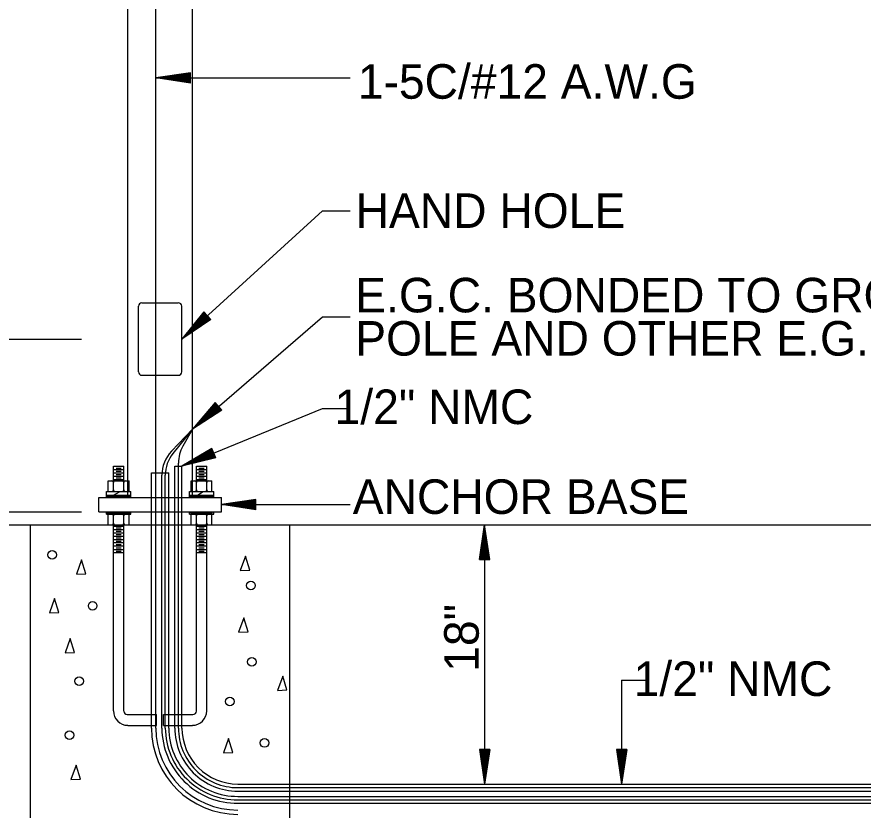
# Model space of a CAD drawing. Extents: x 1695551 to 1695718, y 544410 to 544516.
# Drawn here: x 1695569.58 to 1695587.94, y 544481.31 to 544498.53 of the extents above; entities that cross this region are included whole.
import ezdxf

# ---------------------------------------------------------------- set-up
doc = ezdxf.new("R2010")
doc.units = 0
doc.layers.add('R_Draft', color=7, linetype='Continuous')

msp = doc.modelspace()

# ---------------------------------------------------------------- linework, layer by layer
at = {"layer": 'R_Draft'}
for p, q in [((1695571.983, 544488.101), (1695571.983, 544503.214)), ((1695573.389, 544488.101), (1695573.389, 544503.214)), ((1695572.592, 544483.092), (1695572.592, 544499.584)), ((1695573.343, 544497.321), (1695572.593, 544497.209)), ((1695572.593, 544497.209), (1695576.808, 544497.209)), ((1695573.343, 544497.096), (1695572.593, 544497.209)), ((1695573.343, 544497.302), (1695572.719, 544497.209)), ((1695573.343, 544497.115), (1695572.719, 544497.209)), ((1695573.343, 544497.283), (1695572.848, 544497.209)), ((1695573.343, 544497.134), (1695572.848, 544497.209)), ((1695573.343, 544497.265), (1695572.972, 544497.209)), ((1695573.343, 544497.153), (1695572.972, 544497.209)), ((1695573.343, 544497.245), (1695573.1, 544497.209)), ((1695573.343, 544497.172), (1695573.1, 544497.209)), ((1695573.343, 544497.226), (1695573.225, 544497.209)), ((1695573.343, 544497.191), (1695573.225, 544497.209)), ((1695573.343, 544497.096), (1695573.343, 544497.321)), ((1695573.155, 544491.538), (1695576.207, 544494.32)), ((1695576.207, 544494.32), (1695576.808, 544494.32)), ((1695572.217, 544490.826), (1695572.217, 544492.251)), ((1695572.292, 544492.326), (1695573.08, 544492.326)), ((1695573.155, 544490.826), (1695573.155, 544492.251)), ((1695573.633, 544492.127), (1695573.155, 544491.538)), ((1695573.646, 544492.113), (1695573.247, 544491.623)), ((1695573.658, 544492.099), (1695573.343, 544491.71)), ((1695573.389, 544489.581), (1695576.207, 544492.019)), ((1695573.671, 544492.085), (1695573.435, 544491.794)), ((1695573.684, 544492.071), (1695573.529, 544491.88)), ((1695573.733, 544492.017), (1695573.529, 544491.88)), ((1695573.697, 544492.057), (1695573.621, 544491.964)), ((1695573.721, 544492.031), (1695573.621, 544491.964)), ((1695573.785, 544491.961), (1695573.633, 544492.127)), ((1695576.207, 544492.019), (1695576.808, 544492.019)), ((1695573.785, 544491.961), (1695573.155, 544491.538)), ((1695573.772, 544491.975), (1695573.247, 544491.623)), ((1695573.759, 544491.989), (1695573.343, 544491.71)), ((1695573.746, 544492.003), (1695573.435, 544491.794)), ((1695568.796, 544491.538), (1695570.98, 544491.538)), ((1695572.292, 544490.751), (1695573.08, 544490.751)), ((1695573.161, 544488.775), (1695576.207, 544490.032)), ((1695573.879, 544490.16), (1695573.389, 544489.581)), ((1695574.028, 544489.991), (1695573.389, 544489.581)), ((1695573.892, 544490.146), (1695573.484, 544489.664)), ((1695574.015, 544490.005), (1695573.484, 544489.664)), ((1695573.904, 544490.132), (1695573.581, 544489.749)), ((1695574.003, 544490.019), (1695573.581, 544489.749)), ((1695573.917, 544490.118), (1695573.675, 544489.831)), ((1695573.99, 544490.034), (1695573.675, 544489.831)), ((1695573.929, 544490.103), (1695573.77, 544489.915)), ((1695573.978, 544490.048), (1695573.77, 544489.915)), ((1695573.942, 544490.089), (1695573.864, 544489.998)), ((1695573.965, 544490.062), (1695573.864, 544489.998)), ((1695574.028, 544489.991), (1695573.879, 544490.16)), ((1695576.207, 544490.032), (1695576.808, 544490.032)), ((1695573.389, 544489.581), (1695572.931, 544489.102)), ((1695573.389, 544489.581), (1695572.965, 544489.055)), ((1695573.389, 544489.581), (1695573.181, 544489.214)), ((1695573.812, 544489.165), (1695573.161, 544488.775)), ((1695573.819, 544489.148), (1695573.277, 544488.823)), ((1695573.826, 544489.13), (1695573.396, 544488.872)), ((1695573.833, 544489.113), (1695573.512, 544488.92)), ((1695573.841, 544489.095), (1695573.629, 544488.968)), ((1695573.848, 544489.078), (1695573.745, 544489.016)), ((1695573.897, 544488.957), (1695573.812, 544489.165)), ((1695573.897, 544488.957), (1695573.161, 544488.775)), ((1695573.89, 544488.975), (1695573.277, 544488.823)), ((1695573.883, 544488.992), (1695573.396, 544488.872)), ((1695573.876, 544489.01), (1695573.512, 544488.92)), ((1695573.868, 544489.028), (1695573.629, 544488.968)), ((1695573.861, 544489.045), (1695573.745, 544489.016)), ((1695571.674, 544488.775), (1695571.899, 544488.775)), ((1695571.674, 544488.463), (1695571.674, 544488.775)), ((1695571.674, 544488.703), (1695571.899, 544488.703)), ((1695571.73, 544488.738), (1695571.842, 544488.738)), ((1695571.899, 544488.463), (1695571.899, 544488.775)), ((1695573.005, 544483.092), (1695573.005, 544488.775)), ((1695573.005, 544488.775), (1695573.161, 544488.775)), ((1695573.083, 544483.092), (1695573.083, 544488.844)), ((1695573.161, 544483.092), (1695573.161, 544488.775)), ((1695573.474, 544488.775), (1695573.699, 544488.775)), ((1695573.474, 544488.463), (1695573.474, 544488.775)), ((1695573.474, 544488.703), (1695573.699, 544488.703)), ((1695573.53, 544488.738), (1695573.642, 544488.738)), ((1695573.699, 544488.463), (1695573.699, 544488.775)), ((1695571.674, 544488.631), (1695571.899, 544488.631)), ((1695571.674, 544488.559), (1695571.899, 544488.559)), ((1695571.73, 544488.666), (1695571.842, 544488.666)), ((1695571.73, 544488.594), (1695571.842, 544488.594)), ((1695571.73, 544488.521), (1695571.842, 544488.521)), ((1695572.499, 544483.092), (1695572.499, 544488.631)), ((1695572.499, 544488.631), (1695572.874, 544488.631)), ((1695572.724, 544483.092), (1695572.724, 544488.584)), ((1695572.799, 544483.092), (1695572.799, 544488.584)), ((1695572.874, 544483.092), (1695572.874, 544488.631)), ((1695573.474, 544488.631), (1695573.699, 544488.631)), ((1695573.474, 544488.559), (1695573.699, 544488.559)), ((1695573.53, 544488.666), (1695573.642, 544488.666)), ((1695573.53, 544488.594), (1695573.642, 544488.594)), ((1695573.53, 544488.521), (1695573.642, 544488.521)), ((1695571.561, 544488.226), (1695571.561, 544488.463)), ((1695571.561, 544488.463), (1695572.011, 544488.463)), ((1695571.674, 544488.487), (1695571.899, 544488.487)), ((1695571.674, 544488.226), (1695571.674, 544488.463)), ((1695571.899, 544488.226), (1695571.899, 544488.463)), ((1695572.011, 544488.226), (1695572.011, 544488.463)), ((1695573.361, 544488.226), (1695573.361, 544488.463)), ((1695573.361, 544488.463), (1695573.811, 544488.463)), ((1695573.474, 544488.487), (1695573.699, 544488.487)), ((1695573.474, 544488.226), (1695573.474, 544488.463)), ((1695573.699, 544488.226), (1695573.699, 544488.463)), ((1695573.811, 544488.226), (1695573.811, 544488.463)), ((1695571.524, 544488.101), (1695571.524, 544488.226)), ((1695571.524, 544488.226), (1695572.049, 544488.226)), ((1695571.524, 544488.151), (1695572.049, 544488.151)), ((1695571.524, 544488.124), (1695571.55, 544488.151)), ((1695571.526, 544488.101), (1695571.576, 544488.151)), ((1695571.553, 544488.101), (1695571.603, 544488.151)), ((1695571.579, 544488.101), (1695571.629, 544488.151)), ((1695571.606, 544488.101), (1695571.656, 544488.151)), ((1695571.673, 544488.15), (1695571.805, 544488.224)), ((1695571.674, 544488.112), (1695571.712, 544488.151)), ((1695571.674, 544488.139), (1695571.686, 544488.151)), ((1695571.689, 544488.101), (1695571.739, 544488.151)), ((1695571.715, 544488.101), (1695571.765, 544488.151)), ((1695571.742, 544488.101), (1695571.792, 544488.151)), ((1695571.768, 544488.101), (1695571.818, 544488.151)), ((1695571.795, 544488.101), (1695571.845, 544488.151)), ((1695571.821, 544488.101), (1695571.871, 544488.151)), ((1695571.848, 544488.101), (1695571.898, 544488.151)), ((1695571.899, 544488.119), (1695571.93, 544488.151)), ((1695571.899, 544488.146), (1695571.904, 544488.151)), ((1695571.907, 544488.101), (1695571.957, 544488.151)), ((1695571.933, 544488.101), (1695571.983, 544488.151)), ((1695571.983, 544488.103), (1695572.031, 544488.151)), ((1695571.983, 544488.13), (1695572.004, 544488.151)), ((1695572.049, 544488.101), (1695572.049, 544488.226)), ((1695573.324, 544488.101), (1695573.324, 544488.226)), ((1695573.324, 544488.226), (1695573.849, 544488.226)), ((1695573.324, 544488.151), (1695573.849, 544488.151)), ((1695573.329, 544488.101), (1695573.379, 544488.151)), ((1695573.333, 544488.131), (1695573.353, 544488.151)), ((1695573.389, 544488.116), (1695573.424, 544488.151)), ((1695573.389, 544488.142), (1695573.398, 544488.151)), ((1695573.401, 544488.101), (1695573.451, 544488.151)), ((1695573.474, 544488.114), (1695573.511, 544488.151)), ((1695573.474, 544488.14), (1695573.484, 544488.151)), ((1695573.487, 544488.101), (1695573.537, 544488.151)), ((1695573.497, 544488.151), (1695573.62, 544488.225)), ((1695573.514, 544488.101), (1695573.564, 544488.151)), ((1695573.54, 544488.101), (1695573.59, 544488.151)), ((1695573.567, 544488.101), (1695573.617, 544488.151)), ((1695573.593, 544488.101), (1695573.643, 544488.151)), ((1695573.62, 544488.101), (1695573.67, 544488.151)), ((1695573.646, 544488.101), (1695573.696, 544488.151)), ((1695573.699, 544488.122), (1695573.727, 544488.151)), ((1695573.699, 544488.149), (1695573.701, 544488.151)), ((1695573.704, 544488.101), (1695573.754, 544488.151)), ((1695573.73, 544488.101), (1695573.78, 544488.151)), ((1695573.757, 544488.101), (1695573.807, 544488.151)), ((1695573.783, 544488.101), (1695573.833, 544488.151)), ((1695573.849, 544488.101), (1695573.849, 544488.226)), ((1695571.355, 544487.788), (1695571.355, 544488.101)), ((1695571.355, 544488.101), (1695574.017, 544488.101)), ((1695571.632, 544488.101), (1695571.674, 544488.142)), ((1695571.659, 544488.101), (1695571.674, 544488.115)), ((1695571.874, 544488.101), (1695571.899, 544488.125)), ((1695571.96, 544488.101), (1695571.983, 544488.124)), ((1695572.007, 544488.101), (1695572.049, 544488.142)), ((1695572.034, 544488.101), (1695572.049, 544488.116)), ((1695573.356, 544488.101), (1695573.389, 544488.134)), ((1695573.382, 544488.101), (1695573.389, 544488.108)), ((1695573.427, 544488.101), (1695573.474, 544488.147)), ((1695573.454, 544488.101), (1695573.474, 544488.121)), ((1695573.673, 544488.101), (1695573.699, 544488.127)), ((1695573.81, 544488.101), (1695573.84, 544488.131)), ((1695573.836, 544488.101), (1695573.846, 544488.11)), ((1695574.017, 544487.788), (1695574.017, 544488.101)), ((1695574.767, 544488.057), (1695574.017, 544487.944)), ((1695574.767, 544488.038), (1695574.143, 544487.944)), ((1695574.767, 544488.019), (1695574.272, 544487.944)), ((1695574.767, 544488), (1695574.397, 544487.944)), ((1695574.767, 544487.981), (1695574.524, 544487.944)), ((1695574.767, 544487.832), (1695574.767, 544488.057)), ((1695568.796, 544487.788), (1695570.98, 544487.788)), ((1695571.355, 544487.788), (1695574.017, 544487.788)), ((1695571.524, 544487.738), (1695571.524, 544487.788)), ((1695571.524, 544487.763), (1695571.549, 544487.788)), ((1695571.525, 544487.738), (1695571.575, 544487.788)), ((1695571.552, 544487.738), (1695571.602, 544487.788)), ((1695571.578, 544487.738), (1695571.628, 544487.788)), ((1695571.605, 544487.738), (1695571.655, 544487.788)), ((1695571.674, 544487.749), (1695571.712, 544487.788)), ((1695571.674, 544487.776), (1695571.686, 544487.788)), ((1695571.689, 544487.738), (1695571.739, 544487.788)), ((1695571.715, 544487.738), (1695571.765, 544487.788)), ((1695571.742, 544487.738), (1695571.792, 544487.788)), ((1695571.768, 544487.738), (1695571.818, 544487.788)), ((1695571.795, 544487.738), (1695571.845, 544487.788)), ((1695571.822, 544487.738), (1695571.872, 544487.788)), ((1695571.848, 544487.738), (1695571.898, 544487.788)), ((1695571.899, 544487.738), (1695571.949, 544487.788)), ((1695571.899, 544487.765), (1695571.922, 544487.788)), ((1695571.925, 544487.738), (1695571.975, 544487.788)), ((1695571.952, 544487.738), (1695572.002, 544487.788)), ((1695571.978, 544487.738), (1695572.028, 544487.788)), ((1695572.049, 544487.738), (1695572.049, 544487.788)), ((1695573.324, 544487.738), (1695573.324, 544487.788)), ((1695573.325, 544487.787), (1695573.326, 544487.788)), ((1695573.336, 544487.772), (1695573.353, 544487.788)), ((1695573.347, 544487.756), (1695573.379, 544487.788)), ((1695573.359, 544487.741), (1695573.406, 544487.788)), ((1695573.382, 544487.738), (1695573.432, 544487.788)), ((1695573.409, 544487.738), (1695573.459, 544487.788)), ((1695573.474, 544487.748), (1695573.514, 544487.788)), ((1695573.474, 544487.775), (1695573.487, 544487.788)), ((1695573.49, 544487.738), (1695573.54, 544487.788)), ((1695573.517, 544487.738), (1695573.567, 544487.788)), ((1695573.543, 544487.738), (1695573.593, 544487.788)), ((1695573.57, 544487.738), (1695573.62, 544487.788)), ((1695573.596, 544487.738), (1695573.646, 544487.788)), ((1695573.623, 544487.738), (1695573.673, 544487.788)), ((1695573.649, 544487.738), (1695573.699, 544487.788)), ((1695573.699, 544487.761), (1695573.726, 544487.788)), ((1695573.699, 544487.788), (1695573.699, 544487.788)), ((1695573.702, 544487.738), (1695573.752, 544487.788)), ((1695573.729, 544487.738), (1695573.779, 544487.788)), ((1695573.755, 544487.738), (1695573.805, 544487.788)), ((1695573.782, 544487.738), (1695573.832, 544487.788)), ((1695573.849, 544487.738), (1695573.849, 544487.788)), ((1695574.017, 544487.944), (1695576.808, 544487.944)), ((1695574.767, 544487.832), (1695574.017, 544487.944)), ((1695574.767, 544487.851), (1695574.143, 544487.944)), ((1695574.767, 544487.87), (1695574.272, 544487.944)), ((1695574.767, 544487.888), (1695574.397, 544487.944)), ((1695574.767, 544487.908), (1695574.524, 544487.944)), ((1695574.767, 544487.962), (1695574.649, 544487.944)), ((1695574.767, 544487.927), (1695574.649, 544487.944)), ((1695571.524, 544487.738), (1695572.049, 544487.738)), ((1695571.561, 544487.501), (1695571.561, 544487.738)), ((1695571.631, 544487.738), (1695571.674, 544487.78)), ((1695571.658, 544487.738), (1695571.674, 544487.754)), ((1695571.674, 544487.501), (1695571.674, 544487.738)), ((1695571.875, 544487.738), (1695571.899, 544487.762)), ((1695571.899, 544487.501), (1695571.899, 544487.738)), ((1695572.005, 544487.738), (1695572.049, 544487.782)), ((1695572.011, 544487.501), (1695572.011, 544487.738)), ((1695572.031, 544487.738), (1695572.049, 544487.756)), ((1695573.324, 544487.738), (1695573.849, 544487.738)), ((1695573.361, 544487.501), (1695573.361, 544487.738)), ((1695573.435, 544487.738), (1695573.474, 544487.777)), ((1695573.462, 544487.738), (1695573.474, 544487.75)), ((1695573.474, 544487.501), (1695573.474, 544487.738)), ((1695573.676, 544487.738), (1695573.699, 544487.761)), ((1695573.699, 544487.501), (1695573.699, 544487.738)), ((1695573.808, 544487.738), (1695573.82, 544487.75)), ((1695573.811, 544487.501), (1695573.811, 544487.738)), ((1695559.91, 544487.501), (1695599.544, 544487.501)), ((1695569.874, 544476.251), (1695569.874, 544487.501)), ((1695569.874, 544487.501), (1695575.499, 544487.501)), ((1695571.561, 544487.501), (1695572.011, 544487.501)), ((1695571.674, 544483.463), (1695571.674, 544487.501)), ((1695571.674, 544487.477), (1695571.899, 544487.477)), ((1695571.73, 544487.44), (1695571.842, 544487.44)), ((1695571.899, 544483.46), (1695571.899, 544487.501)), ((1695573.361, 544487.501), (1695573.811, 544487.501)), ((1695573.474, 544483.46), (1695573.474, 544487.501)), ((1695573.474, 544487.477), (1695573.699, 544487.477)), ((1695573.53, 544487.44), (1695573.642, 544487.44)), ((1695573.699, 544483.463), (1695573.699, 544487.501)), ((1695575.499, 544476.251), (1695575.499, 544487.501)), ((1695579.615, 544486.751), (1695579.727, 544487.501)), ((1695579.727, 544487.501), (1695579.727, 544481.876)), ((1695579.84, 544486.751), (1695579.727, 544487.501)), ((1695571.674, 544487.405), (1695571.899, 544487.405)), ((1695571.674, 544487.333), (1695571.899, 544487.333)), ((1695571.674, 544487.261), (1695571.899, 544487.261)), ((1695571.73, 544487.368), (1695571.842, 544487.368)), ((1695571.73, 544487.295), (1695571.842, 544487.295)), ((1695573.474, 544487.405), (1695573.699, 544487.405)), ((1695573.474, 544487.333), (1695573.699, 544487.333)), ((1695573.474, 544487.261), (1695573.699, 544487.261)), ((1695573.53, 544487.368), (1695573.642, 544487.368)), ((1695573.53, 544487.295), (1695573.642, 544487.295)), ((1695579.633, 544486.751), (1695579.727, 544487.376)), ((1695579.653, 544486.751), (1695579.727, 544487.247)), ((1695579.821, 544486.751), (1695579.727, 544487.376)), ((1695579.802, 544486.751), (1695579.727, 544487.247)), ((1695571.674, 544487.189), (1695571.899, 544487.189)), ((1695571.674, 544487.117), (1695571.899, 544487.117)), ((1695571.73, 544487.223), (1695571.842, 544487.223)), ((1695571.73, 544487.151), (1695571.842, 544487.151)), ((1695571.73, 544487.079), (1695571.842, 544487.079)), ((1695573.474, 544487.189), (1695573.699, 544487.189)), ((1695573.474, 544487.117), (1695573.699, 544487.117)), ((1695573.53, 544487.223), (1695573.642, 544487.223)), ((1695573.53, 544487.151), (1695573.642, 544487.151)), ((1695573.53, 544487.079), (1695573.642, 544487.079)), ((1695579.671, 544486.751), (1695579.727, 544487.122)), ((1695579.783, 544486.751), (1695579.727, 544487.122)), ((1695571.674, 544487.045), (1695571.899, 544487.045)), ((1695571.674, 544486.972), (1695571.899, 544486.972)), ((1695571.674, 544486.9), (1695571.899, 544486.9)), ((1695571.73, 544487.007), (1695571.842, 544487.007)), ((1695571.73, 544486.935), (1695571.842, 544486.935)), ((1695573.474, 544487.045), (1695573.699, 544487.045)), ((1695573.474, 544486.972), (1695573.699, 544486.972)), ((1695573.474, 544486.9), (1695573.699, 544486.9)), ((1695573.53, 544487.007), (1695573.642, 544487.007)), ((1695573.53, 544486.935), (1695573.642, 544486.935)), ((1695579.691, 544486.751), (1695579.727, 544486.995)), ((1695579.71, 544486.751), (1695579.727, 544486.87)), ((1695579.764, 544486.751), (1695579.727, 544486.995)), ((1695579.745, 544486.751), (1695579.727, 544486.87)), ((1695579.615, 544486.751), (1695579.84, 544486.751)), ((1695582.703, 544484.128), (1695582.703, 544481.876)), ((1695582.703, 544484.128), (1695583.299, 544484.128)), ((1695571.974, 544483.385), (1695572.611, 544483.385)), ((1695572.611, 544483.15), (1695572.611, 544483.385)), ((1695572.761, 544483.15), (1695572.761, 544483.385)), ((1695572.761, 544483.385), (1695573.399, 544483.385)), ((1695571.986, 544483.15), (1695572.611, 544483.15)), ((1695572.761, 544483.15), (1695573.386, 544483.15)), ((1695579.615, 544482.626), (1695579.727, 544481.876)), ((1695579.84, 544482.626), (1695579.615, 544482.626)), ((1695579.633, 544482.626), (1695579.727, 544482.002)), ((1695579.653, 544482.626), (1695579.727, 544482.131)), ((1695579.671, 544482.626), (1695579.727, 544482.255)), ((1695579.69, 544482.626), (1695579.727, 544482.383)), ((1695579.71, 544482.626), (1695579.727, 544482.508)), ((1695579.84, 544482.626), (1695579.727, 544481.876)), ((1695579.764, 544482.626), (1695579.727, 544482.383)), ((1695579.802, 544482.626), (1695579.727, 544482.131)), ((1695579.821, 544482.626), (1695579.727, 544482.002)), ((1695579.783, 544482.626), (1695579.727, 544482.255)), ((1695579.745, 544482.626), (1695579.727, 544482.508)), ((1695582.591, 544482.626), (1695582.703, 544481.876)), ((1695582.816, 544482.626), (1695582.591, 544482.626)), ((1695582.61, 544482.626), (1695582.703, 544482.002)), ((1695582.629, 544482.626), (1695582.703, 544482.131)), ((1695582.647, 544482.626), (1695582.703, 544482.255)), ((1695582.667, 544482.626), (1695582.703, 544482.383)), ((1695582.686, 544482.626), (1695582.703, 544482.508)), ((1695582.816, 544482.626), (1695582.703, 544481.876)), ((1695582.74, 544482.626), (1695582.703, 544482.383)), ((1695582.778, 544482.626), (1695582.703, 544482.131)), ((1695582.797, 544482.626), (1695582.703, 544482.002)), ((1695582.759, 544482.626), (1695582.703, 544482.255)), ((1695582.721, 544482.626), (1695582.703, 544482.508)), ((1695574.374, 544481.876), (1695592.925, 544481.876)), ((1695574.374, 544481.798), (1695592.74, 544481.798)), ((1695574.374, 544481.72), (1695592.925, 544481.72)), ((1695574.374, 544481.608), (1695592.925, 544481.608)), ((1695574.374, 544481.533), (1695593.965, 544481.533)), ((1695574.374, 544481.458), (1695593.42, 544481.458))]:
    msp.add_line(p, q, dxfattribs=at)
for points in [[(1695570.982, 544486.741), (1695570.869, 544486.43), (1695571.075, 544486.438), (1695570.982, 544486.741)], [(1695574.539, 544486.825), (1695574.426, 544486.514), (1695574.632, 544486.523), (1695574.539, 544486.825)], [(1695570.396, 544485.902), (1695570.282, 544485.591), (1695570.489, 544485.6), (1695570.396, 544485.902)], [(1695574.502, 544485.483), (1695574.389, 544485.172), (1695574.595, 544485.18), (1695574.502, 544485.483)], [(1695570.737, 544485.033), (1695570.623, 544484.722), (1695570.83, 544484.73), (1695570.737, 544485.033)], [(1695575.346, 544484.221), (1695575.232, 544483.91), (1695575.439, 544483.918), (1695575.346, 544484.221)], [(1695574.173, 544482.864), (1695574.059, 544482.553), (1695574.266, 544482.561), (1695574.173, 544482.864)], [(1695570.863, 544482.287), (1695570.749, 544481.976), (1695570.955, 544481.985), (1695570.863, 544482.287)]]:
    msp.add_lwpolyline(points, dxfattribs=at)
for centre in [(1695570.342, 544486.855), (1695574.658, 544486.185), (1695571.222, 544485.744), (1695574.679, 544484.529), (1695570.929, 544484.109), (1695574.197, 544483.669), (1695570.719, 544482.936), (1695574.951, 544482.768)]:
    msp.add_circle(centre, 0.0937, dxfattribs=at)
for centre, radius, start, end in [((1695572.292, 544492.251), 0.075, 90, 180), ((1695573.08, 544492.251), 0.075, 360, 90), ((1695572.292, 544490.826), 0.075, 180, 270), ((1695573.08, 544490.826), 0.075, 270, 0), ((1695573.474, 544488.584), 0.75, 136.323, 180), ((1695573.833, 544488.844), 0.75, 150.4069, 180), ((1695573.549, 544488.584), 0.75, 141.118, 180), ((1695571.636, 544488.425), 0.0375, 0, 90), ((1695571.711, 544488.425), 0.0375, 90, 180), ((1695571.861, 544488.425), 0.0375, 0, 90), ((1695571.936, 544488.425), 0.0375, 90, 180), ((1695573.436, 544488.425), 0.0375, 0, 90), ((1695573.511, 544488.425), 0.0375, 90, 180), ((1695573.661, 544488.425), 0.0375, 0, 90), ((1695573.736, 544488.425), 0.0375, 90, 180), ((1695571.636, 544488.263), 0.0375, 270, 0), ((1695571.711, 544488.263), 0.0375, 180, 270), ((1695571.861, 544488.263), 0.0375, 270, 0), ((1695571.936, 544488.263), 0.0375, 180, 270), ((1695573.436, 544488.263), 0.0375, 270, 0), ((1695573.511, 544488.263), 0.0375, 180, 270), ((1695573.661, 544488.263), 0.0375, 270, 0), ((1695573.736, 544488.263), 0.0375, 180, 270), ((1695571.636, 544487.701), 0.0375, 0, 90), ((1695571.711, 544487.701), 0.0375, 90, 180), ((1695571.861, 544487.701), 0.0375, 0, 90), ((1695571.936, 544487.701), 0.0375, 90, 180), ((1695573.436, 544487.701), 0.0375, 0, 90), ((1695573.511, 544487.701), 0.0375, 90, 180), ((1695573.661, 544487.701), 0.0375, 0, 90), ((1695573.736, 544487.701), 0.0375, 90, 180), ((1695571.636, 544487.539), 0.0375, 270, 0), ((1695571.711, 544487.539), 0.0375, 180, 270), ((1695571.861, 544487.539), 0.0375, 270, 0), ((1695571.936, 544487.539), 0.0375, 180, 270), ((1695573.436, 544487.539), 0.0375, 270, 0), ((1695573.511, 544487.539), 0.0375, 180, 270), ((1695573.661, 544487.539), 0.0375, 270, 0), ((1695573.736, 544487.539), 0.0375, 180, 270), ((1695571.986, 544483.463), 0.312, 180, 270), ((1695571.974, 544483.46), 0.075, 180, 270), ((1695573.386, 544483.463), 0.312, 270, 0), ((1695573.399, 544483.46), 0.075, 270, 0), ((1695574.374, 544483.092), 1.875, 180, 270), ((1695574.374, 544483.092), 1.781, 180, 270), ((1695574.366, 544483.1), 1.642, 180.3, 270.3), ((1695574.366, 544483.1), 1.567, 180.3, 270.3), ((1695574.366, 544483.1), 1.492, 180.3, 270.3), ((1695574.375, 544483.09), 1.37, 179.9347, 269.9347), ((1695574.375, 544483.09), 1.292, 179.9263, 269.9263), ((1695574.375, 544483.09), 1.214, 179.9263, 269.9263)]:
    msp.add_arc(centre, radius, start, end, dxfattribs=at)

# ---------------------------------------------------------------- texts
for s, p in [('1-5C/#12 A.W.G', (1695576.977, 544496.756)), ('HAND HOLE', (1695576.929, 544493.951)), ('E.G.C. BONDED TO GROUND LUG ON ', (1695576.921, 544492.117)), ('POLE AND OTHER E.G.C. CONDUCTORS', (1695576.921, 544491.178)), (' 1/2" NMC ', (1695576.195, 544489.692)), ('ANCHOR BASE', (1695576.867, 544487.741)), (' 1/2" NMC ', (1695582.685, 544483.788))]:
    msp.add_text(s, height=0.75, dxfattribs=at).set_placement(p)
msp.add_text('18"', height=0.75, rotation=90, dxfattribs=at).set_placement((1695579.601, 544484.314))

doc.saveas('drawing.dxf')
